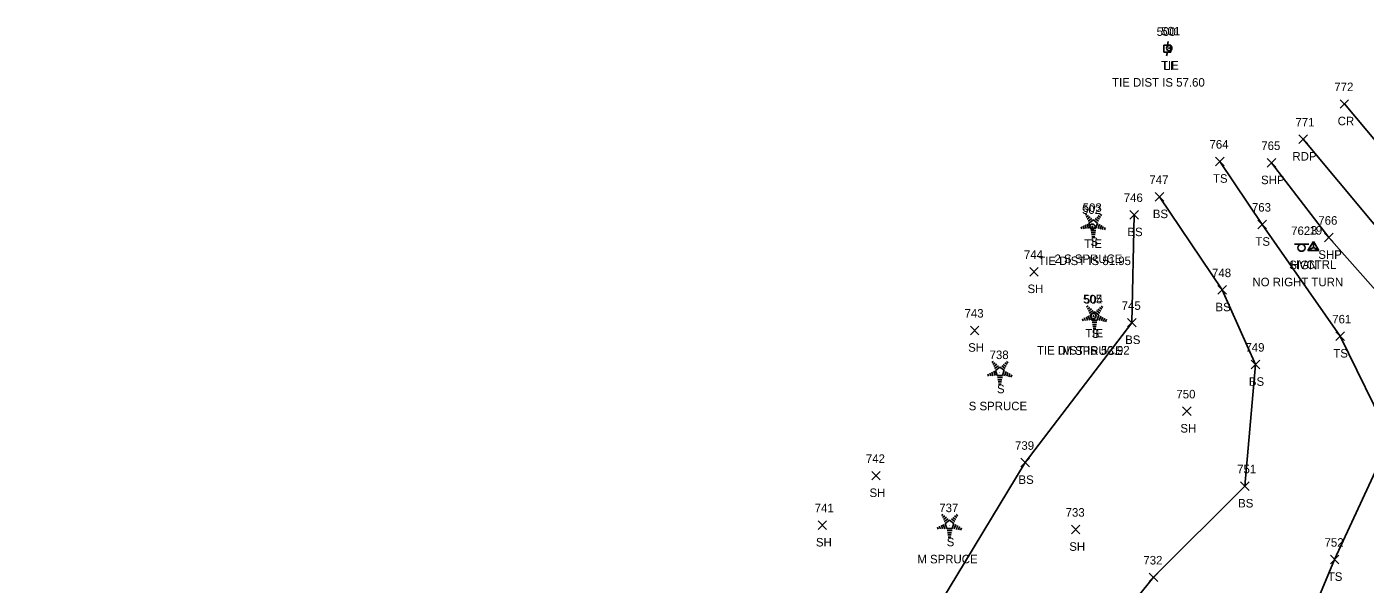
# Model space of a CAD drawing. Extents: x 1688195 to 1692013, y 424605 to 441234.
# Drawn here: x 1691404.7 to 1691718.1, y 439274 to 439404.6 of the extents above; entities that cross this region are included whole.
import ezdxf

# ---------------------------------------------------------------- set-up
doc = ezdxf.new("R2010")
doc.units = 0
for name, color, linetype in [('C_A', 7, 'Continuous'), ('C_C', 7, 'Continuous'), ('C_I', 7, 'Continuous'), ('CBP', 7, 'Continuous'), ('CPSM', 7, 'Continuous'), ('L_A', 7, 'Continuous'), ('L_C', 7, 'Continuous'), ('L_I', 7, 'Continuous'), ('L_TIC', 7, 'Continuous'), ('LELB', 7, 'Continuous'), ('LTC', 7, 'Continuous'), ('P_A', 7, 'Continuous'), ('P_I', 7, 'Continuous'), ('P_TIC', 7, 'Continuous'), ('PET', 7, 'Continuous'), ('PRC', 7, 'Continuous'), ('PSP', 7, 'Continuous'), ('S_A', 7, 'Continuous'), ('S_C', 7, 'Continuous'), ('S_I', 7, 'Continuous'), ('SSGN', 7, 'Continuous'), ('U_A', 7, 'Continuous'), ('U_I', 7, 'Continuous'), ('ULP', 7, 'Continuous')]:
    doc.layers.add(name, color=color, linetype=linetype)

msp = doc.modelspace()

# ---------------------------------------------------------------- linework, layer by layer
at = {"layer": 'CBP'}
for centre, radius in [((1691672.17, 439399.54), 0.625), ((1691672.17, 439399.54), 0.0833), ((1691654.18, 439357.73), 0.625), ((1691654.18, 439357.73), 0.0833), ((1691654.43, 439336.78), 0.625), ((1691654.43, 439336.78), 0.0833)]:
    msp.add_circle(centre, radius, dxfattribs=at)
at = {"layer": 'CPSM'}
for p, q in [((1691704.66, 439352.12), (1691705.91, 439354.29)), ((1691704.66, 439352.12), (1691705.91, 439354.29)), ((1691704.66, 439352.12), (1691705.91, 439354.29)), ((1691704.66, 439352.13), (1691705.91, 439354.29)), ((1691707.16, 439352.12), (1691705.91, 439354.29)), ((1691705.91, 439352.84), (1691705.91, 439354.29)), ((1691707.16, 439352.12), (1691705.91, 439354.29)), ((1691705.91, 439352.84), (1691705.91, 439354.29)), ((1691707.16, 439352.12), (1691705.91, 439354.29)), ((1691705.91, 439352.84), (1691705.91, 439354.29)), ((1691707.16, 439352.13), (1691705.91, 439354.29)), ((1691705.91, 439352.85), (1691705.91, 439354.29)), ((1691704.66, 439352.13), (1691705.91, 439352.85)), ((1691704.66, 439352.12), (1691705.91, 439352.84)), ((1691704.66, 439352.12), (1691705.91, 439352.84)), ((1691704.66, 439352.12), (1691705.91, 439352.84)), ((1691704.66, 439352.13), (1691707.16, 439352.13)), ((1691704.66, 439352.12), (1691707.16, 439352.12)), ((1691704.66, 439352.12), (1691707.16, 439352.12)), ((1691704.66, 439352.12), (1691707.16, 439352.12)), ((1691705.91, 439352.85), (1691705.91, 439352.85)), ((1691705.91, 439352.85), (1691707.16, 439352.13)), ((1691705.91, 439352.84), (1691705.91, 439352.84)), ((1691705.91, 439352.84), (1691707.16, 439352.12)), ((1691705.91, 439352.84), (1691705.91, 439352.84)), ((1691705.91, 439352.84), (1691707.16, 439352.12)), ((1691705.91, 439352.84), (1691705.91, 439352.84)), ((1691705.91, 439352.84), (1691707.16, 439352.12))]:
    msp.add_line(p, q, dxfattribs=at)
at = {"layer": 'L_TIC'}
for points in [[(1691683, 439372.02), (1691685, 439374.02)], [(1691685, 439372.02), (1691683, 439374.02)], [(1691668.89, 439363.73), (1691670.89, 439365.73)], [(1691670.89, 439363.73), (1691668.89, 439365.73)], [(1691662.94, 439359.51), (1691664.94, 439361.51)], [(1691664.94, 439359.51), (1691662.94, 439361.51)], [(1691692.94, 439357.26), (1691694.94, 439359.26)], [(1691694.94, 439357.26), (1691692.94, 439359.26)], [(1691639.5, 439346.17), (1691641.5, 439348.17)], [(1691641.5, 439346.17), (1691639.5, 439348.17)], [(1691683.56, 439341.91), (1691685.56, 439343.91)], [(1691685.56, 439341.91), (1691683.56, 439343.91)], [(1691662.4, 439334.24), (1691664.4, 439336.24)], [(1691664.4, 439334.24), (1691662.4, 439336.24)], [(1691625.6, 439332.43), (1691627.6, 439334.43)], [(1691627.6, 439332.43), (1691625.6, 439334.43)], [(1691711.17, 439331.07), (1691713.17, 439333.07)], [(1691713.17, 439331.07), (1691711.17, 439333.07)], [(1691691.38, 439324.45), (1691693.38, 439326.45)], [(1691693.38, 439324.45), (1691691.38, 439326.45)], [(1691675.29, 439313.5), (1691677.29, 439315.5)], [(1691677.29, 439313.5), (1691675.29, 439315.5)], [(1691637.43, 439301.46), (1691639.43, 439303.46)], [(1691639.43, 439301.46), (1691637.43, 439303.46)], [(1691602.5, 439298.39), (1691604.5, 439300.39)], [(1691604.5, 439298.39), (1691602.5, 439300.39)], [(1691688.85, 439295.94), (1691690.85, 439297.94)], [(1691690.85, 439295.94), (1691688.85, 439297.94)], [(1691688.85, 439295.94), (1691690.85, 439297.94)], [(1691690.85, 439295.94), (1691688.85, 439297.94)], [(1691589.95, 439286.81), (1691591.95, 439288.81)], [(1691591.95, 439286.81), (1691589.95, 439288.81)], [(1691649.27, 439285.79), (1691651.27, 439287.79)], [(1691651.27, 439285.79), (1691649.27, 439287.79)], [(1691709.89, 439278.75), (1691711.89, 439280.75)], [(1691711.89, 439278.75), (1691709.89, 439280.75)], [(1691667.47, 439274.59), (1691669.47, 439276.59)], [(1691669.47, 439274.59), (1691667.47, 439276.59)]]:
    msp.add_lwpolyline(points, dxfattribs=at)
at = {"layer": 'LELB'}
for points in [[(1691372.73, 438902.64), (1691398.57, 438929.63), (1691421.61, 438954.81), (1691450.5, 438984.08), (1691477.46, 439013.34), (1691508.26, 439046.52), (1691540.85, 439082.44), (1691568.31, 439110.72), (1691593.69, 439141.21), (1691622.93, 439171.73), (1691652.84, 439206.76), (1691674.71, 439229.19), (1691701.22, 439256.48), (1691710.89, 439279.75), (1691723.95, 439307.99), (1691712.17, 439332.07), (1691693.94, 439358.26), (1691684, 439373.02)], [(1691669.89, 439364.73), (1691684.56, 439342.91), (1691692.38, 439325.45), (1691689.85, 439296.94)], [(1691525.69, 439149.58), (1691548.83, 439176.28), (1691571.85, 439208.37), (1691601.9, 439243.82), (1691616.58, 439266.33), (1691638.43, 439302.46), (1691663.4, 439335.24), (1691663.94, 439360.51)], [(1691652.84, 439256.18), (1691668.47, 439275.59), (1691689.85, 439296.94)]]:
    msp.add_lwpolyline(points, dxfattribs=at)
at = {"layer": 'LTC'}
for p, q in [((1691652.53, 439360.42), (1691652.89, 439360.68)), ((1691652.74, 439359.95), (1691653.27, 439360.34)), ((1691655.56, 439360.31), (1691656.11, 439359.91)), ((1691655.93, 439360.66), (1691656.35, 439360.35)), ((1691651.56, 439357.7), (1691651.72, 439357.23)), ((1691652.02, 439357.91), (1691652.23, 439357.26)), ((1691652.47, 439358.13), (1691652.75, 439357.3)), ((1691652.93, 439358.35), (1691653.26, 439357.33)), ((1691652.95, 439359.49), (1691653.65, 439360)), ((1691653.16, 439359.02), (1691654.04, 439359.66)), ((1691653.38, 439358.57), (1691654.4, 439359.3)), ((1691653.38, 439358.57), (1691653.77, 439357.37)), ((1691655, 439357.37), (1691653.77, 439357.37)), ((1691654.4, 439359.3), (1691655.39, 439358.58)), ((1691654.82, 439359.61), (1691655.63, 439359.03)), ((1691655.39, 439358.58), (1691655, 439357.37)), ((1691655.19, 439359.96), (1691655.87, 439359.47)), ((1691655.83, 439358.31), (1691655.49, 439357.27)), ((1691656.28, 439358.06), (1691655.99, 439357.17)), ((1691656.72, 439357.81), (1691656.48, 439357.08)), ((1691657.16, 439357.55), (1691656.98, 439356.98)), ((1691654.96, 439356.87), (1691653.82, 439356.87)), ((1691654.88, 439356.37), (1691653.89, 439356.37)), ((1691654.8, 439355.87), (1691653.96, 439355.87)), ((1691654.71, 439355.37), (1691654.04, 439355.37)), ((1691652.82, 439338.89), (1691653.17, 439339.15)), ((1691653.03, 439338.43), (1691653.56, 439338.81)), ((1691653.24, 439337.96), (1691653.94, 439338.47)), ((1691653.45, 439337.5), (1691654.33, 439338.13)), ((1691655.47, 439338.44), (1691656.15, 439337.94)), ((1691655.85, 439338.78), (1691656.4, 439338.39)), ((1691656.22, 439339.13), (1691656.64, 439338.83)), ((1691651.85, 439336.17), (1691652, 439335.7)), ((1691652.31, 439336.39), (1691652.52, 439335.74)), ((1691652.76, 439336.61), (1691653.03, 439335.77)), ((1691653.22, 439336.82), (1691653.55, 439335.8)), ((1691653.67, 439337.04), (1691654.68, 439337.78)), ((1691653.67, 439337.04), (1691654.06, 439335.85)), ((1691655.29, 439335.85), (1691654.06, 439335.85)), ((1691655.25, 439335.35), (1691654.11, 439335.35)), ((1691654.68, 439337.78), (1691655.68, 439337.05)), ((1691655.1, 439338.09), (1691655.91, 439337.5)), ((1691655.68, 439337.05), (1691655.29, 439335.85)), ((1691656.12, 439336.78), (1691655.78, 439335.74)), ((1691656.56, 439336.53), (1691656.28, 439335.64)), ((1691657.01, 439336.28), (1691656.77, 439335.55)), ((1691657.45, 439336.03), (1691657.26, 439335.45)), ((1691655.17, 439334.85), (1691654.18, 439334.85)), ((1691655.08, 439334.35), (1691654.25, 439334.35)), ((1691655, 439333.85), (1691654.32, 439333.85)), ((1691630.66, 439325.92), (1691631.02, 439326.18)), ((1691630.87, 439325.45), (1691631.4, 439325.84)), ((1691633.69, 439325.81), (1691634.24, 439325.41)), ((1691634.06, 439326.16), (1691634.48, 439325.85)), ((1691629.69, 439323.2), (1691629.85, 439322.73)), ((1691630.15, 439323.41), (1691630.36, 439322.76)), ((1691630.61, 439323.63), (1691630.88, 439322.8)), ((1691631.06, 439323.85), (1691631.39, 439322.83)), ((1691631.08, 439324.99), (1691631.78, 439325.5)), ((1691631.29, 439324.52), (1691632.17, 439325.16)), ((1691631.52, 439324.07), (1691632.53, 439324.8)), ((1691631.52, 439324.07), (1691631.9, 439322.87)), ((1691633.13, 439322.87), (1691631.9, 439322.87)), ((1691632.53, 439324.8), (1691633.52, 439324.08)), ((1691632.95, 439325.11), (1691633.76, 439324.53)), ((1691633.52, 439324.08), (1691633.13, 439322.87)), ((1691633.32, 439325.46), (1691634, 439324.97)), ((1691633.96, 439323.81), (1691633.62, 439322.77)), ((1691634.41, 439323.56), (1691634.12, 439322.67)), ((1691634.85, 439323.31), (1691634.61, 439322.58)), ((1691635.29, 439323.05), (1691635.11, 439322.48)), ((1691633.09, 439322.37), (1691631.95, 439322.37)), ((1691633.01, 439321.87), (1691632.02, 439321.87)), ((1691632.93, 439321.37), (1691632.1, 439321.37)), ((1691632.84, 439320.87), (1691632.17, 439320.87)), ((1691618.87, 439290.06), (1691619.23, 439290.32)), ((1691619.08, 439289.6), (1691619.61, 439289.98)), ((1691619.27, 439287.99), (1691619.6, 439286.97)), ((1691619.29, 439289.13), (1691620, 439289.64)), ((1691619.5, 439288.67), (1691620.38, 439289.3)), ((1691619.73, 439288.21), (1691620.74, 439288.95)), ((1691619.73, 439288.21), (1691620.12, 439287.02)), ((1691620.74, 439288.95), (1691621.74, 439288.22)), ((1691621.16, 439289.26), (1691621.97, 439288.67)), ((1691621.74, 439288.22), (1691621.35, 439287.02)), ((1691621.53, 439289.61), (1691622.21, 439289.11)), ((1691622.17, 439287.95), (1691621.84, 439286.91)), ((1691621.9, 439289.96), (1691622.45, 439289.56)), ((1691622.27, 439290.3), (1691622.69, 439290)), ((1691617.91, 439287.34), (1691618.06, 439286.87)), ((1691618.36, 439287.56), (1691618.57, 439286.91)), ((1691618.82, 439287.78), (1691619.09, 439286.94)), ((1691621.35, 439287.02), (1691620.12, 439287.02)), ((1691621.31, 439286.52), (1691620.16, 439286.52)), ((1691621.22, 439286.02), (1691620.24, 439286.02)), ((1691621.14, 439285.52), (1691620.31, 439285.52)), ((1691621.06, 439285.02), (1691620.38, 439285.02)), ((1691622.62, 439287.7), (1691622.33, 439286.81)), ((1691623.06, 439287.45), (1691622.83, 439286.72)), ((1691623.51, 439287.2), (1691623.32, 439286.62))]:
    msp.add_line(p, q, dxfattribs=at)
at = {"layer": 'P_TIC'}
for points in [[(1691712.18, 439385.48), (1691714.18, 439387.48)], [(1691714.18, 439385.48), (1691712.18, 439387.48)], [(1691702.52, 439377.21), (1691704.52, 439379.21)], [(1691704.52, 439377.21), (1691702.52, 439379.21)], [(1691695.13, 439371.69), (1691697.13, 439373.69)], [(1691697.13, 439371.69), (1691695.13, 439373.69)], [(1691708.55, 439354.19), (1691710.55, 439356.19)], [(1691710.55, 439354.19), (1691708.55, 439356.19)]]:
    msp.add_lwpolyline(points, dxfattribs=at)
at = {"layer": 'PET'}
msp.add_lwpolyline([(1691703.52, 439378.21), (1691727.93, 439348.96), (1691752.51, 439320.77), (1691774.83, 439296.79), (1691803.99, 439267.94), (1691829.7, 439246.01), (1691860.19, 439220.26)], dxfattribs=at)
at = {"layer": 'PRC'}
msp.add_lwpolyline([(1691713.18, 439386.48), (1691737.31, 439357.71), (1691761.17, 439330.74), (1691784.31, 439305.52), (1691812.13, 439278.2), (1691838.3, 439254.51), (1691867.44, 439230.25), (1691889.26, 439214.41), (1691920.44, 439189.8), (1691954.55, 439163.68)], dxfattribs=at)
at = {"layer": 'PSP'}
msp.add_lwpolyline([(1691696.13, 439372.69), (1691709.55, 439355.19), (1691723.6, 439339.32), (1691742.75, 439319), (1691750.97, 439309.53), (1691763.38, 439297.71), (1691773.94, 439286.94), (1691807.32, 439260.15), (1691827.22, 439244.92), (1691853.91, 439221.37)], dxfattribs=at)
at = {"layer": 'SSGN'}
for p, q in [((1691701.5, 439353.63), (1691704.83, 439353.63)), ((1691703.14, 439352.79), (1691703.14, 439352.79))]:
    msp.add_line(p, q, dxfattribs=at)
msp.add_circle((1691703.14, 439352.79), 0.833, dxfattribs=at)
at = {"layer": 'ULP'}
for p, q in [((1691671.91, 439401.1), (1691671.74, 439400.26)), ((1691670.91, 439398.6), (1691670.91, 439400.26)), ((1691670.91, 439400.26), (1691672.58, 439400.26)), ((1691672.58, 439398.6), (1691670.91, 439398.6)), ((1691671.49, 439397.76), (1691671.74, 439398.6)), ((1691671.74, 439399.43), (1691671.74, 439399.43)), ((1691672.58, 439400.26), (1691672.58, 439398.6))]:
    msp.add_line(p, q, dxfattribs=at)

# ---------------------------------------------------------------- texts
at = {"layer": 'C_A'}
for s, p in [('TIE', (1691670.25, 439394.54)), ('TIE', (1691652.26, 439352.73)), ('HVCTRL', (1691700.6, 439347.85)), ('HVCTRL', (1691700.6, 439347.85)), ('HVCTRL', (1691700.6, 439347.85)), ('HVCTRL', (1691700.6, 439347.85)), ('TIE', (1691652.51, 439331.78))]:
    msp.add_text(s, height=2, dxfattribs=at).set_placement(p)
at = {"layer": 'C_C'}
for s, p in [('TIE DIST IS 57.60', (1691658.79, 439390.54)), ('TIE DIST IS 51.95', (1691641.5, 439348.73)), ('TIE DIST IS 53.92', (1691641.19, 439327.78))]:
    msp.add_text(s, height=2, dxfattribs=at).set_placement(p)
at = {"layer": 'C_I'}
for s, p in [('501', (1691670.3, 439402.54)), ('502', (1691651.74, 439360.73)), ('19', (1691705, 439355.85)), ('3', (1691705.34, 439355.85)), ('3', (1691705.34, 439355.85)), ('3', (1691705.34, 439355.85)), ('505', (1691651.99, 439339.78))]:
    msp.add_text(s, height=2, dxfattribs=at).set_placement(p)
at = {"layer": 'L_A'}
for s, p in [('TS', (1691682.41, 439368.02)), ('BS', (1691668.33, 439359.73)), ('BS', (1691662.38, 439355.51)), ('S', (1691653.72, 439353.21)), ('TS', (1691692.35, 439353.26)), ('SH', (1691638.99, 439342.17)), ('BS', (1691683, 439337.91)), ('S', (1691654.01, 439331.68)), ('BS', (1691661.85, 439330.24)), ('SH', (1691625.09, 439328.43)), ('TS', (1691710.58, 439327.07)), ('BS', (1691690.82, 439320.45)), ('S', (1691631.85, 439318.71)), ('SH', (1691674.78, 439309.5)), ('BS', (1691636.87, 439297.46)), ('SH', (1691601.99, 439294.39)), ('BS', (1691688.3, 439291.94)), ('BS', (1691688.3, 439291.94)), ('SH', (1691589.44, 439282.81)), ('S', (1691620.07, 439282.85)), ('SH', (1691648.76, 439281.79)), ('TS', (1691709.3, 439274.75))]:
    msp.add_text(s, height=2, dxfattribs=at).set_placement(p)
at = {"layer": 'L_C'}
for s, p in [('2 S SPRUCE', (1691645.3, 439349.21)), ('M SPRUCE', (1691647.13, 439327.68)), ('S SPRUCE', (1691625.22, 439314.71)), ('M SPRUCE', (1691613.18, 439278.85))]:
    msp.add_text(s, height=2, dxfattribs=at).set_placement(p)
at = {"layer": 'L_I'}
for s, p in [('764', (1691681.59, 439376.02)), ('747', (1691667.52, 439367.73)), ('503', (1691651.9, 439361.21)), ('746', (1691661.52, 439363.51)), ('763', (1691691.53, 439361.26)), ('744', (1691638.14, 439350.17)), ('748', (1691682.19, 439345.91)), ('504', (1691652.18, 439339.68)), ('743', (1691624.24, 439336.43)), ('745', (1691661.04, 439338.24)), ('761', (1691710.33, 439335.07)), ('738', (1691630.1, 439326.71)), ('749', (1691690.01, 439328.45)), ('750', (1691673.84, 439317.5)), ('739', (1691636.06, 439305.46)), ('742', (1691601.14, 439302.39)), ('751', (1691688.06, 439299.94)), ('751', (1691688.06, 439299.94)), ('741', (1691589.15, 439290.81)), ('737', (1691618.32, 439290.85)), ('733', (1691647.91, 439289.79)), ('752', (1691708.53, 439282.75)), ('732', (1691666.11, 439278.59))]:
    msp.add_text(s, height=2, dxfattribs=at).set_placement(p)
at = {"layer": 'LTC'}
for p in [(1691654.28, 439358.31), (1691654.57, 439336.79), (1691632.41, 439323.81), (1691620.62, 439287.96)]:
    msp.add_text('.', height=1.04, rotation=270, dxfattribs=at).set_placement(p)
at = {"layer": 'P_A'}
for s, p in [('CR', (1691711.61, 439381.48)), ('RDP', (1691701.01, 439373.21)), ('SHP', (1691693.67, 439367.69)), ('SHP', (1691707.08, 439350.19))]:
    msp.add_text(s, height=2, dxfattribs=at).set_placement(p)
at = {"layer": 'P_I'}
for s, p in [('772', (1691710.82, 439389.48)), ('771', (1691701.72, 439381.21)), ('765', (1691693.72, 439375.69)), ('766', (1691707.08, 439358.19))]:
    msp.add_text(s, height=2, dxfattribs=at).set_placement(p)
at = {"layer": 'S_A'}
msp.add_text('SIGN', height=2, dxfattribs=at).set_placement((1691700.28, 439347.77))
at = {"layer": 'S_C'}
msp.add_text('NO RIGHT TURN', height=2, dxfattribs=at).set_placement((1691691.65, 439343.77))
at = {"layer": 'S_I'}
msp.add_text('762', height=2, dxfattribs=at).set_placement((1691700.71, 439355.77))
at = {"layer": 'U_A'}
msp.add_text('LI', height=2, dxfattribs=at).set_placement((1691670.85, 439394.43))
at = {"layer": 'U_I'}
msp.add_text('500', height=2, dxfattribs=at).set_placement((1691669.22, 439402.43))

doc.saveas('drawing.dxf')
